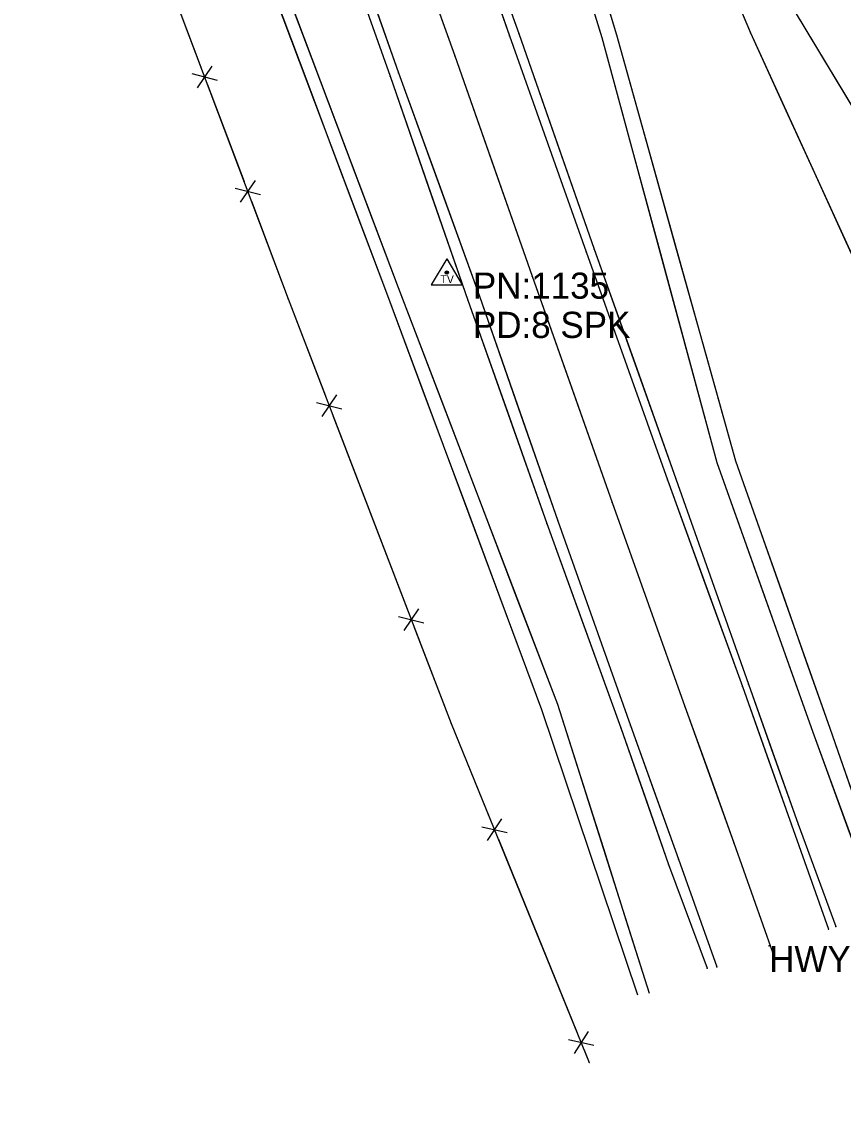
# Model space of a CAD drawing. Extents: x 1050807 to 1053552, y 395828 to 398415.
# Drawn here: x 1052633.5 to 1052790.6, y 395828.1 to 396034.9 of the extents above; entities that cross this region are included whole.
import ezdxf

# ---------------------------------------------------------------- set-up
doc = ezdxf.new("R2010")
doc.units = 0
for name, color, linetype in [('S_DITCHLINE', 7, 'Continuous'), ('S_DRIVEWAY', 7, 'Continuous'), ('S_EDGE_PAVEMENT', 7, 'Continuous'), ('S_FENCE', 7, 'Continuous'), ('S_MSC_PT_SYM', 7, 'Continuous'), ('S_PAVEMENT_CROWN', 7, 'Continuous'), ('S_RDW_PT_SYM', 7, 'Continuous'), ('S_SECONDARY_CTL', 7, 'Continuous'), ('S_SECONDARY_CTL_ANNOT', 7, 'Continuous'), ('S_SHOULDER', 7, 'Continuous'), ('S_SURVEY_TEXT_ANNOT', 7, 'Continuous')]:
    doc.layers.add(name, color=color, linetype=linetype)

msp = doc.modelspace()

# ---------------------------------------------------------------- linework, layer by layer
at = {"layer": 'S_DITCHLINE'}
for p, q in [((1052725.19, 396106.59), (1052747.18, 396032.38)), ((1052721.92, 396104.47), (1052744.4, 396031.88)), ((1052663.51, 396088.42), (1052703.24, 395983.02)), ((1052665.73, 396089.35), (1052705.46, 395984.05)), ((1052747.18, 396032.38), (1052769.95, 395950.91)), ((1052744.4, 396031.88), (1052766.38, 395950.62)), ((1052703.24, 395983.02), (1052732.85, 395903.39)), ((1052705.46, 395984.05), (1052735.92, 395904.41)), ((1052766.38, 395950.62), (1052784.72, 395899.06)), ((1052769.95, 395950.91), (1052788.01, 395899.83)), ((1052735.92, 395904.41), (1052753.46, 395849.2)), ((1052732.85, 395903.39), (1052751.2, 395848.85)), ((1052788.01, 395899.83), (1052812.63, 395828.64)), ((1052784.72, 395899.06), (1052810.64, 395828.11))]:
    msp.add_line(p, q, dxfattribs=at)
for points in [[(1052667.19, 396235.17), (1052672.63, 396217.62), (1052682.66, 396199.25), (1052692.68, 396180.88), (1052699.99, 396161.78), (1052707.3, 396142.68), (1052714.61, 396123.58), (1052721.92, 396104.47), (1052727.54, 396086.32), (1052733.16, 396068.18), (1052738.78, 396050.03), (1052744.4, 396031.88), (1052749.9, 396011.56), (1052755.39, 395991.25), (1052760.89, 395970.94), (1052766.38, 395950.62), (1052770.97, 395937.73), (1052775.55, 395924.84), (1052780.13, 395911.95), (1052784.72, 395899.06), (1052791.2, 395881.32), (1052797.68, 395863.58), (1052804.16, 395845.85), (1052810.64, 395828.11)], [(1052669.02, 396235.8), (1052675.04, 396219.02), (1052684.79, 396200.32), (1052694.54, 396181.62), (1052702.2, 396162.86), (1052709.86, 396144.1), (1052717.52, 396125.35), (1052725.19, 396106.59), (1052730.68, 396088.04), (1052736.18, 396069.48), (1052741.68, 396050.93), (1052747.18, 396032.38), (1052752.87, 396012.01), (1052758.56, 395991.64), (1052764.26, 395971.28), (1052769.95, 395950.91), (1052774.46, 395938.14), (1052778.98, 395925.37), (1052783.49, 395912.6), (1052788.01, 395899.83), (1052794.16, 395882.03), (1052800.32, 395864.23), (1052806.48, 395846.43), (1052812.63, 395828.64)], [(1052620.07, 396227.58), (1052627.48, 396205.25), (1052634.89, 396182.92), (1052642.05, 396159.3), (1052649.2, 396135.67), (1052656.36, 396112.05), (1052663.51, 396088.42), (1052668.48, 396075.25), (1052673.44, 396062.07), (1052678.41, 396048.9), (1052683.38, 396035.72), (1052688.34, 396022.55), (1052693.31, 396009.37), (1052698.27, 395996.19), (1052703.24, 395983.02), (1052710.64, 395963.11), (1052718.05, 395943.2), (1052725.45, 395923.3), (1052732.85, 395903.39), (1052737.44, 395889.76), (1052742.03, 395876.12), (1052746.61, 395862.49), (1052751.2, 395848.85)], [(1052620.81, 396227.93), (1052628.79, 396205.73), (1052636.76, 396183.53), (1052644, 396159.99), (1052651.24, 396136.44), (1052658.48, 396112.9), (1052665.73, 396089.35), (1052670.69, 396076.19), (1052675.66, 396063.03), (1052680.63, 396049.86), (1052685.59, 396036.7), (1052690.56, 396023.54), (1052695.53, 396010.38), (1052700.49, 395997.21), (1052705.46, 395984.05), (1052713.07, 395964.14), (1052720.69, 395944.23), (1052728.3, 395924.32), (1052735.92, 395904.41), (1052740.3, 395890.61), (1052744.69, 395876.8), (1052749.07, 395863), (1052753.46, 395849.2)]]:
    msp.add_lwpolyline(points, dxfattribs=at)
at = {"layer": 'S_DRIVEWAY'}
for p, q in [((1052739.52, 396111.91), (1052772.8, 396032.74)), ((1052781.19, 396037.02), (1052810.9, 395987.58)), ((1052772.8, 396032.74), (1052797.15, 395979.49))]:
    msp.add_line(p, q, dxfattribs=at)
for points in [[(1052659.6, 396252.65), (1052670.75, 396253.48), (1052686.97, 396247.75), (1052693.36, 396241.69), (1052703.81, 396231.56), (1052710.61, 396211.53), (1052717.4, 396191.5), (1052724.49, 396172.29), (1052731.58, 396153.08), (1052738.66, 396133.87), (1052745.75, 396114.65), (1052754.61, 396095.25), (1052763.47, 396075.84), (1052772.33, 396056.43), (1052781.19, 396037.02), (1052788.62, 396024.66), (1052796.05, 396012.3), (1052803.47, 395999.94), (1052810.9, 395987.58), (1052815.52, 395970.22), (1052820.46, 395954.63), (1052808.41, 395951.52)], [(1052664.49, 396242.14), (1052673.01, 396242.35), (1052682.55, 396239.86), (1052689.21, 396234.92), (1052695.83, 396227.71), (1052702.87, 396208.25), (1052709.91, 396188.79), (1052717.31, 396169.57), (1052724.71, 396150.35), (1052732.11, 396131.13), (1052739.52, 396111.91), (1052747.84, 396092.12), (1052756.16, 396072.33), (1052764.48, 396052.53), (1052772.8, 396032.74), (1052778.89, 396019.43), (1052784.98, 396006.11), (1052791.06, 395992.8), (1052797.15, 395979.49), (1052804.07, 395963.29), (1052808.41, 395951.52)]]:
    msp.add_lwpolyline(points, dxfattribs=at)
at = {"layer": 'S_EDGE_PAVEMENT'}
for p, q in [((1052712.3, 396073.21), (1052726.77, 396032.18)), ((1052691.54, 396064.73), (1052705.54, 396025.11)), ((1052726.77, 396032.18), (1052741.39, 395990.85)), ((1052705.54, 396025.11), (1052720.98, 395982.38)), ((1052741.39, 395990.85), (1052756.93, 395947.29)), ((1052720.98, 395982.38), (1052736.01, 395939.48)), ((1052756.93, 395947.29), (1052771.28, 395907.81)), ((1052736.01, 395939.48), (1052749.87, 395900.35)), ((1052771.28, 395907.81), (1052780.63, 395881.38)), ((1052749.87, 395900.35), (1052759.05, 395874.76)), ((1052780.63, 395881.38), (1052787.73, 395861.44)), ((1052759.05, 395874.76), (1052766.38, 395854.19))]:
    msp.add_line(p, q, dxfattribs=at)
for points in [[(1052623.98, 396255.21), (1052629.2, 396240.35), (1052634.42, 396225.5), (1052641.29, 396206.33), (1052648.17, 396187.15), (1052655.4, 396166.58), (1052662.63, 396146), (1052669.81, 396125.89), (1052676.99, 396105.79), (1052684.26, 396085.26), (1052691.54, 396064.73), (1052698.54, 396044.92), (1052705.54, 396025.11), (1052713.26, 396003.75), (1052720.98, 395982.38), (1052728.49, 395960.93), (1052736.01, 395939.48), (1052742.94, 395919.92), (1052749.87, 395900.35), (1052754.46, 395887.56), (1052759.05, 395874.76), (1052766.38, 395854.19)], [(1052649.92, 396248.39), (1052655.12, 396233.76), (1052661.96, 396214.34), (1052668.81, 396194.91), (1052676.12, 396174.41), (1052683.44, 396153.91), (1052690.62, 396133.61), (1052697.8, 396113.32), (1052705.05, 396093.26), (1052712.3, 396073.21), (1052719.54, 396052.69), (1052726.77, 396032.18), (1052734.08, 396011.52), (1052741.39, 395990.85), (1052749.16, 395969.07), (1052756.93, 395947.29), (1052764.11, 395927.55), (1052771.28, 395907.81), (1052775.95, 395894.59), (1052780.63, 395881.38), (1052787.73, 395861.44)]]:
    msp.add_lwpolyline(points, dxfattribs=at)
at = {"layer": 'S_FENCE'}
for p, q in [((1052645.22, 396085.99), (1052684.41, 395981.91)), ((1052669.85, 396026.39), (1052667.03, 396022.26)), ((1052666.02, 396024.94), (1052670.86, 396023.71)), ((1052678.1, 396004.49), (1052675.27, 396000.37)), ((1052674.26, 396003.05), (1052679.11, 396001.81)), ((1052684.41, 395981.91), (1052715.57, 395900.75)), ((1052689.84, 395962.07), (1052694.68, 395960.87)), ((1052693.66, 395963.53), (1052690.86, 395959.4)), ((1052709.36, 395922.65), (1052706.56, 395918.51)), ((1052705.53, 395921.18), (1052710.38, 395919.98)), ((1052715.57, 395900.75), (1052742, 395835.95)), ((1052725.21, 395882.52), (1052722.5, 395878.33)), ((1052721.42, 395880.98), (1052726.29, 395879.87)), ((1052741.79, 395841.87), (1052739.08, 395837.67)), ((1052738, 395840.32), (1052742.87, 395839.22))]:
    msp.add_line(p, q, dxfattribs=at)
for points in [[(1052653.66, 396063.56), (1052667.74, 396026.19)], [(1052668.94, 396022.99), (1052675.98, 396004.3)], [(1052677.39, 396000.56), (1052684.41, 395981.91)], [(1052684.41, 395981.91), (1052691.55, 395963.33)], [(1052692.97, 395959.61), (1052707.24, 395922.44)], [(1052708.47, 395919.25), (1052715.57, 395900.75)], [(1052715.57, 395900.75), (1052723.1, 395882.27)], [(1052724.61, 395878.58), (1052739.68, 395841.62)], [(1052740.98, 395838.45), (1052742, 395835.95)]]:
    msp.add_lwpolyline(points, dxfattribs=at)
at = {"layer": 'S_MSC_PT_SYM'}
for points in [[(1052684.41, 395981.91), (1052684.41, 395981.96), (1052684.41, 395981.91), (1052684.36, 395981.91), (1052684.41, 395981.91), (1052684.41, 395981.86), (1052684.41, 395981.91), (1052684.46, 395981.91)], [(1052715.57, 395900.75), (1052715.57, 395900.8), (1052715.57, 395900.75), (1052715.52, 395900.75), (1052715.57, 395900.75), (1052715.57, 395900.7), (1052715.57, 395900.75), (1052715.62, 395900.75)], [(1052776.39, 395858.21), (1052776.39, 395858.26), (1052776.39, 395858.21), (1052776.34, 395858.21), (1052776.39, 395858.21), (1052776.39, 395858.16), (1052776.39, 395858.21), (1052776.44, 395858.21)], [(1052742, 395835.95), (1052742, 395836), (1052742, 395835.95), (1052741.95, 395835.95), (1052742, 395835.95), (1052742, 395835.9), (1052742, 395835.95), (1052742.05, 395835.95)]]:
    msp.add_lwpolyline(points, dxfattribs=at)
at = {"layer": 'S_PAVEMENT_CROWN'}
for p, q in [((1052701.59, 396069.26), (1052716.29, 396028.33)), ((1052716.29, 396028.33), (1052731.06, 395986.23)), ((1052731.06, 395986.23), (1052746.35, 395942.97)), ((1052746.35, 395942.97), (1052760.26, 395904)), ((1052760.26, 395904), (1052769.66, 395877.9)), ((1052769.66, 395877.9), (1052777.01, 395857.04))]:
    msp.add_line(p, q, dxfattribs=at)
msp.add_lwpolyline([(1052639.65, 396244.64), (1052644.91, 396230.01), (1052651.77, 396210.45), (1052658.64, 396190.89), (1052665.78, 396170.34), (1052672.91, 396149.79), (1052680.2, 396129.33), (1052687.49, 396108.87), (1052694.54, 396089.07), (1052701.59, 396069.26), (1052708.94, 396048.8), (1052716.29, 396028.33), (1052723.67, 396007.28), (1052731.06, 395986.23), (1052738.71, 395964.6), (1052746.35, 395942.97), (1052753.3, 395923.48), (1052760.26, 395904), (1052764.96, 395890.95), (1052769.66, 395877.9), (1052777.01, 395857.04)], dxfattribs=at)
at = {"layer": 'S_RDW_PT_SYM'}
for points in [[(1052726.77, 396032.18), (1052726.77, 396032.23), (1052726.77, 396032.18), (1052726.72, 396032.18), (1052726.77, 396032.18), (1052726.77, 396032.13), (1052726.77, 396032.18), (1052726.82, 396032.18)], [(1052728.52, 396032.59), (1052728.52, 396032.64), (1052728.52, 396032.59), (1052728.47, 396032.59), (1052728.52, 396032.59), (1052728.52, 396032.54), (1052728.52, 396032.59), (1052728.57, 396032.59)], [(1052772.8, 396032.74), (1052772.8, 396032.79), (1052772.8, 396032.74), (1052772.75, 396032.74), (1052772.8, 396032.74), (1052772.8, 396032.69), (1052772.8, 396032.74), (1052772.85, 396032.74)], [(1052716.29, 396028.33), (1052716.29, 396028.38), (1052716.29, 396028.33), (1052716.24, 396028.33), (1052716.29, 396028.33), (1052716.29, 396028.28), (1052716.29, 396028.33), (1052716.34, 396028.33)], [(1052703.9, 396024.43), (1052703.9, 396024.48), (1052703.9, 396024.43), (1052703.85, 396024.43), (1052703.9, 396024.43), (1052703.9, 396024.38), (1052703.9, 396024.43), (1052703.95, 396024.43)], [(1052705.54, 396025.11), (1052705.54, 396025.16), (1052705.54, 396025.11), (1052705.49, 396025.11), (1052705.54, 396025.11), (1052705.54, 396025.06), (1052705.54, 396025.11), (1052705.59, 396025.11)], [(1052741.39, 395990.85), (1052741.39, 395990.9), (1052741.39, 395990.85), (1052741.34, 395990.85), (1052741.39, 395990.85), (1052741.39, 395990.8), (1052741.39, 395990.85), (1052741.44, 395990.85)], [(1052742.95, 395991.39), (1052742.95, 395991.44), (1052742.95, 395991.39), (1052742.9, 395991.39), (1052742.95, 395991.39), (1052742.95, 395991.34), (1052742.95, 395991.39), (1052743, 395991.39)], [(1052731.06, 395986.23), (1052731.06, 395986.28), (1052731.06, 395986.23), (1052731.01, 395986.23), (1052731.06, 395986.23), (1052731.06, 395986.18), (1052731.06, 395986.23), (1052731.11, 395986.23)], [(1052720.98, 395982.38), (1052720.98, 395982.43), (1052720.98, 395982.38), (1052720.93, 395982.38), (1052720.98, 395982.38), (1052720.98, 395982.33), (1052720.98, 395982.38), (1052721.03, 395982.38)], [(1052718.79, 395981.67), (1052718.79, 395981.72), (1052718.79, 395981.67), (1052718.74, 395981.67), (1052718.79, 395981.67), (1052718.79, 395981.62), (1052718.79, 395981.67), (1052718.84, 395981.67)], [(1052756.93, 395947.29), (1052756.93, 395947.34), (1052756.93, 395947.29), (1052756.88, 395947.29), (1052756.93, 395947.29), (1052756.93, 395947.24), (1052756.93, 395947.29), (1052756.98, 395947.29)], [(1052758.57, 395947.51), (1052758.57, 395947.56), (1052758.57, 395947.51), (1052758.52, 395947.51), (1052758.57, 395947.51), (1052758.57, 395947.46), (1052758.57, 395947.51), (1052758.62, 395947.51)], [(1052746.35, 395942.97), (1052746.35, 395943.02), (1052746.35, 395942.97), (1052746.3, 395942.97), (1052746.35, 395942.97), (1052746.35, 395942.92), (1052746.35, 395942.97), (1052746.4, 395942.97)], [(1052733.88, 395938.93), (1052733.88, 395938.98), (1052733.88, 395938.93), (1052733.83, 395938.93), (1052733.88, 395938.93), (1052733.88, 395938.88), (1052733.88, 395938.93), (1052733.93, 395938.93)], [(1052736.01, 395939.48), (1052736.01, 395939.53), (1052736.01, 395939.48), (1052735.96, 395939.48), (1052736.01, 395939.48), (1052736.01, 395939.43), (1052736.01, 395939.48), (1052736.06, 395939.48)], [(1052772.43, 395908.25), (1052772.43, 395908.3), (1052772.43, 395908.25), (1052772.38, 395908.25), (1052772.43, 395908.25), (1052772.43, 395908.2), (1052772.43, 395908.25), (1052772.48, 395908.25)], [(1052771.28, 395907.81), (1052771.28, 395907.86), (1052771.28, 395907.81), (1052771.23, 395907.81), (1052771.28, 395907.81), (1052771.28, 395907.76), (1052771.28, 395907.81), (1052771.33, 395907.81)], [(1052760.26, 395904), (1052760.26, 395904.05), (1052760.26, 395904), (1052760.21, 395904), (1052760.26, 395904), (1052760.26, 395903.95), (1052760.26, 395904), (1052760.31, 395904)], [(1052748.04, 395899.9), (1052748.04, 395899.95), (1052748.04, 395899.9), (1052747.99, 395899.9), (1052748.04, 395899.9), (1052748.04, 395899.85), (1052748.04, 395899.9), (1052748.09, 395899.9)], [(1052749.87, 395900.35), (1052749.87, 395900.4), (1052749.87, 395900.35), (1052749.82, 395900.35), (1052749.87, 395900.35), (1052749.87, 395900.3), (1052749.87, 395900.35), (1052749.92, 395900.35)], [(1052780.63, 395881.38), (1052780.63, 395881.43), (1052780.63, 395881.38), (1052780.58, 395881.38), (1052780.63, 395881.38), (1052780.63, 395881.33), (1052780.63, 395881.38), (1052780.68, 395881.38)], [(1052781.93, 395881.51), (1052781.93, 395881.56), (1052781.93, 395881.51), (1052781.88, 395881.51), (1052781.93, 395881.51), (1052781.93, 395881.46), (1052781.93, 395881.51), (1052781.98, 395881.51)], [(1052769.66, 395877.9), (1052769.66, 395877.95), (1052769.66, 395877.9), (1052769.61, 395877.9), (1052769.66, 395877.9), (1052769.66, 395877.85), (1052769.66, 395877.9), (1052769.71, 395877.9)], [(1052757.15, 395873.79), (1052757.15, 395873.84), (1052757.15, 395873.79), (1052757.1, 395873.79), (1052757.15, 395873.79), (1052757.15, 395873.74), (1052757.15, 395873.79), (1052757.2, 395873.79)], [(1052759.05, 395874.76), (1052759.05, 395874.81), (1052759.05, 395874.76), (1052759, 395874.76), (1052759.05, 395874.76), (1052759.05, 395874.71), (1052759.05, 395874.76), (1052759.1, 395874.76)], [(1052787.73, 395861.44), (1052787.73, 395861.49), (1052787.73, 395861.44), (1052787.68, 395861.44), (1052787.73, 395861.44), (1052787.73, 395861.39), (1052787.73, 395861.44), (1052787.78, 395861.44)], [(1052789.15, 395861.89), (1052789.15, 395861.94), (1052789.15, 395861.89), (1052789.1, 395861.89), (1052789.15, 395861.89), (1052789.15, 395861.84), (1052789.15, 395861.89), (1052789.2, 395861.89)], [(1052777.01, 395857.04), (1052777.01, 395857.09), (1052777.01, 395857.04), (1052776.96, 395857.04), (1052777.01, 395857.04), (1052777.01, 395856.99), (1052777.01, 395857.04), (1052777.06, 395857.04)], [(1052766.38, 395854.19), (1052766.38, 395854.24), (1052766.38, 395854.19), (1052766.33, 395854.19), (1052766.38, 395854.19), (1052766.38, 395854.14), (1052766.38, 395854.19), (1052766.43, 395854.19)], [(1052764.55, 395853.95), (1052764.55, 395854), (1052764.55, 395853.95), (1052764.5, 395853.95), (1052764.55, 395853.95), (1052764.55, 395853.9), (1052764.55, 395853.95), (1052764.6, 395853.95)]]:
    msp.add_lwpolyline(points, dxfattribs=at)
at = {"layer": 'S_SECONDARY_CTL'}
for p, q in [((1052714.75, 395989.53), (1052711.74, 395984.57)), ((1052714.75, 395989.53), (1052717.69, 395984.57)), ((1052711.74, 395984.57), (1052717.69, 395984.57))]:
    msp.add_line(p, q, dxfattribs=at)
for radius in [0.311, 0.183, 0.103]:
    msp.add_circle((1052714.75, 395986.92), radius, dxfattribs=at)
at = {"layer": 'S_SHOULDER'}
for p, q in [((1052713.62, 396074.37), (1052728.52, 396032.59)), ((1052689.75, 396064.34), (1052703.9, 396024.43)), ((1052728.52, 396032.59), (1052742.95, 395991.39)), ((1052703.9, 396024.43), (1052718.79, 395981.67)), ((1052742.95, 395991.39), (1052758.57, 395947.51)), ((1052718.79, 395981.67), (1052733.88, 395938.93)), ((1052758.57, 395947.51), (1052772.43, 395908.25)), ((1052733.88, 395938.93), (1052748.04, 395899.9)), ((1052772.43, 395908.25), (1052781.93, 395881.51)), ((1052748.04, 395899.9), (1052757.15, 395873.79)), ((1052781.93, 395881.51), (1052789.15, 395861.89)), ((1052757.15, 395873.79), (1052764.55, 395853.95))]:
    msp.add_line(p, q, dxfattribs=at)
for points in [[(1052657.67, 396236.53), (1052657.5, 396234.32), (1052664.06, 396214.72), (1052670.62, 396195.12), (1052677.82, 396174.89), (1052685.02, 396154.66), (1052692.1, 396134.37), (1052699.17, 396114.07), (1052706.4, 396094.22), (1052713.62, 396074.37), (1052721.07, 396053.48), (1052728.52, 396032.59), (1052735.74, 396011.99), (1052742.95, 395991.39), (1052750.76, 395969.45), (1052758.57, 395947.51), (1052765.5, 395927.88), (1052772.43, 395908.25), (1052777.18, 395894.88), (1052781.93, 395881.51), (1052789.15, 395861.89)], [(1052629.12, 396231.28), (1052630.77, 396230.22), (1052632.79, 396224.61), (1052639.78, 396205.57), (1052646.77, 396186.52), (1052653.85, 396166), (1052660.94, 396145.49), (1052668.04, 396125.3), (1052675.13, 396105.12), (1052682.44, 396084.73), (1052689.75, 396064.34), (1052696.82, 396044.39), (1052703.9, 396024.43), (1052711.34, 396003.05), (1052718.79, 395981.67), (1052726.33, 395960.3), (1052733.88, 395938.93), (1052740.96, 395919.42), (1052748.04, 395899.9), (1052752.59, 395886.84), (1052757.15, 395873.79), (1052764.55, 395853.95)]]:
    msp.add_lwpolyline(points, dxfattribs=at)

# ---------------------------------------------------------------- texts
at = {"layer": 'S_SECONDARY_CTL'}
msp.add_text('TV', height=1.5, dxfattribs=at).set_placement((1052713.54, 395984.9))
at = {"layer": 'S_SECONDARY_CTL_ANNOT'}
for s, p in [('PN:1135', (1052719.75, 395981.92)), ('PD:8 SPK', (1052719.75, 395974.42))]:
    msp.add_text(s, height=5, dxfattribs=at).set_placement(p)
at = {"layer": 'S_SURVEY_TEXT_ANNOT'}
msp.add_text('HWY.124', height=5, dxfattribs=at).set_placement((1052776.39, 395853.21))

doc.saveas('drawing.dxf')
